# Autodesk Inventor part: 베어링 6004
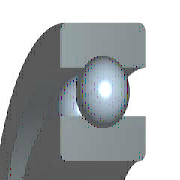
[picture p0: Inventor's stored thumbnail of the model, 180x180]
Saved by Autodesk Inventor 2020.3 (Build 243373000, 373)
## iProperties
Created: 2012-02
Part Number: 베어링 6004
Material: 강철, 연강
Description: 깊은 그루브 볼 베어링
Document SubType Name: Modeling
Standard: KS B 2023
Designer: mduedu
Standards Organization: KS
Language: ko-KR
Size Designation: 6004 - 20 x 42 x 12
Categories: <MemberInstance><Categories><Category DisplayName="샤프트 부품" InternalName="7f7aeb1f-a693-4053-b835-cee3144e0d98" Mnemonic="SHFT"><Category DisplayName="베어링" Inter
Density: 1 g/cm^3
Appearance: 노란색
IsCustomPart: 1
Author: mduedu
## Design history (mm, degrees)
sketch "스케치" dims "d0" = 5.72 (= -0.26 x WD + 0.26 x BD)
  geometry: L1 (3.14, 15.5)-(8.86, 15.5); L2 (6, 15.5)-(6, 12.64); L3 (6, 15.5)-(6, 18.36); L4 (3.875, 13.586)-(0, 13.586); L5 (0, 10)-(12, 10); L6 (3.875, 17.414)-(0, 17.414); L7 (0, 21)-(12, 21); L8 (12, 10)-(12, 13.586); L9 (8.125, 13.586)-(12, 13.586); L10 (8.125, 17.414)-(12, 17.414); L11 (12, 21)-(12, 17.414); L12 (-1.4, 0)-(8.4, 0) reference; L13 (0, -0.3)-(0, 5.3) reference
  constraints: 22 end point, 4 point on line, 2 collinear, 2 perpendicular, 2 symmetric about line, 1 midpoint, 1 parallel, 14 other
  dimensions: "d9" = 20 diameter of L5 L12 (= WD); "d11" = 42 diameter of L7 L12 (= BD); "d12" = 12 distance between parallel lines of L8 L13 (= KB); "d13" = 27.172 diameter of L9 L12 (= 0.326 x BD + 0.674 x WD)
revolve "본체" stored, may be unused: angle "d6" = 90 deg
revolve "볼" stored, may be unused: angle "d7" = 90 deg
pattern_circular "IDS_ARRAYBALL[SIMPL:T]" dims angle "d3" = 360 deg
body "Solid1"
fillet "모깎기1" dims "d1" = 0.6 (= KRS)
other parameters: "WD" = 20 [user parameter; used in 5 equation terms], "BD" = 42 [user parameter; used in 5 equation terms], "KB" = 12 [user parameter; used in 1 equation term], "KRS" = 0.6 [user parameter; used in 1 equation term], "d4" = 0, "d5" = 0, "d8" = 0, "d14" = 0, "d15" = 0, "BBA" = 0 [user parameter], "BC0" = 5000000 [user parameter], "BC" = 9360000 [user parameter], "BR" = 21 (= 0.5 x BD) [user parameter]
